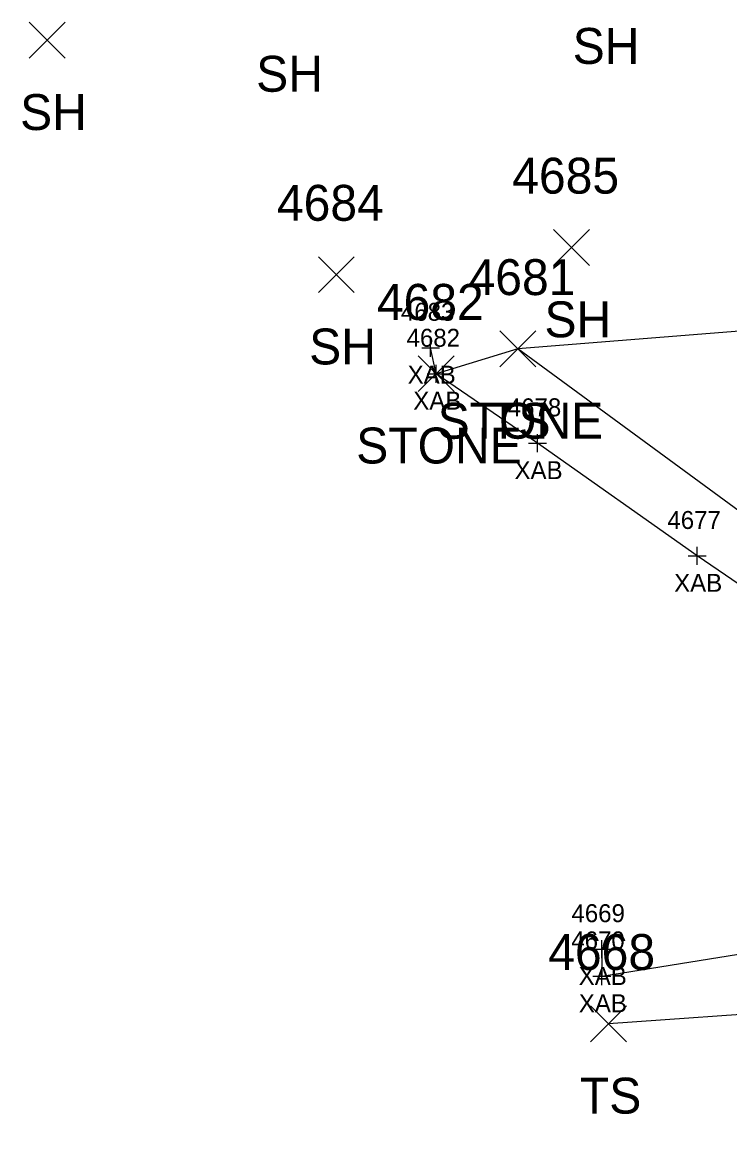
# Model space of a CAD drawing. Extents: x 1505656 to 1508446, y 700805 to 703031.
# Drawn here: x 1507022.6 to 1507061.9, y 701609.6 to 701671.6 of the extents above; entities that cross this region are included whole.
import ezdxf

# ---------------------------------------------------------------- set-up
doc = ezdxf.new("R2010")
doc.units = 0
for name, color, linetype in [('B_A', 7, 'Continuous'), ('B_I', 7, 'Continuous'), ('B_TIC', 7, 'Continuous'), ('BSUBM', 7, 'Continuous'), ('L_A', 7, 'Continuous'), ('L_I', 7, 'Continuous'), ('L_TIC', 7, 'Continuous'), ('LASF', 7, 'Continuous'), ('LELB', 7, 'Continuous')]:
    doc.layers.add(name, color=color, linetype=linetype)

msp = doc.modelspace()

# ---------------------------------------------------------------- linework, layer by layer
at = {"layer": 'B_TIC'}
for p, q in [((1507045.299, 701653.515), (1507045.374, 701653.515)), ((1507045.613, 701652.067), (1507045.688, 701652.067)), ((1507051.247, 701648.195), (1507051.323, 701648.195)), ((1507060.132, 701641.92), (1507060.207, 701641.92)), ((1507054.82, 701620.021), (1507054.895, 701620.021)), ((1507054.826, 701618.506), (1507054.901, 701618.506))]:
    msp.add_line(p, q, dxfattribs=at)
for points in [[(1507045.296, 701653.015), (1507045.296, 701654.015)], [(1507044.796, 701653.515), (1507045.796, 701653.515)], [(1507045.609, 701651.567), (1507045.609, 701652.567)], [(1507045.109, 701652.067), (1507046.109, 701652.067)], [(1507051.244, 701647.695), (1507051.244, 701648.695)], [(1507050.744, 701648.195), (1507051.744, 701648.195)], [(1507060.128, 701641.42), (1507060.128, 701642.42)], [(1507059.628, 701641.92), (1507060.628, 701641.92)], [(1507054.816, 701619.521), (1507054.816, 701620.521)], [(1507054.316, 701620.021), (1507055.316, 701620.021)], [(1507054.322, 701618.506), (1507055.322, 701618.506)], [(1507054.822, 701618.006), (1507054.822, 701619.006)]]:
    msp.add_lwpolyline(points, dxfattribs=at)
at = {"layer": 'BSUBM'}
msp.add_lwpolyline([(1507054.816, 701620.021), (1507054.822, 701618.506), (1507072.232, 701621.324), (1507084.922, 701623.311), (1507084.728, 701624.83), (1507078.817, 701628.967), (1507069.887, 701635.267), (1507060.128, 701641.92), (1507051.244, 701648.195), (1507045.609, 701652.067), (1507045.296, 701653.515)], dxfattribs=at)
at = {"layer": 'L_TIC'}
for points in [[(1507022.956, 701669.639), (1507024.956, 701671.639)], [(1507024.956, 701669.639), (1507022.956, 701671.639)], [(1507052.143, 701658.095), (1507054.143, 701660.095)], [(1507054.143, 701658.095), (1507052.143, 701660.095)], [(1507039.045, 701656.583), (1507041.045, 701658.583)], [(1507041.045, 701656.583), (1507039.045, 701658.583)], [(1507049.145, 701652.446), (1507051.145, 701654.446)], [(1507051.145, 701652.446), (1507049.145, 701654.446)], [(1507049.145, 701652.446), (1507051.145, 701654.446)], [(1507051.145, 701652.446), (1507049.145, 701654.446)], [(1507044.609, 701651.067), (1507046.609, 701653.067)], [(1507046.609, 701651.067), (1507044.609, 701653.067)], [(1507054.194, 701614.86), (1507056.194, 701616.86)], [(1507056.194, 701614.86), (1507054.194, 701616.86)]]:
    msp.add_lwpolyline(points, dxfattribs=at)
at = {"layer": 'LASF'}
msp.add_lwpolyline([(1507078.86, 701653.961), (1507068.999, 701654.953), (1507050.145, 701653.446), (1507045.609, 701652.067)], dxfattribs=at)
at = {"layer": 'LELB'}
for points in [[(1507091.83, 701624.828), (1507067.274, 701640.893), (1507050.145, 701653.446)], [(1507142.5, 701612.027), (1507115.939, 701613.729), (1507092.309, 701609.573), (1507076.307, 701618.116), (1507065.723, 701616.607), (1507055.194, 701615.86)]]:
    msp.add_lwpolyline(points, dxfattribs=at)

# ---------------------------------------------------------------- texts
at = {"layer": 'B_A'}
for p in [(1507044.016, 701651.515), (1507044.33, 701650.067), (1507049.964, 701646.195), (1507058.849, 701639.92), (1507053.537, 701618.021), (1507053.543, 701616.506)]:
    msp.add_text('XAB', height=1, dxfattribs=at).set_placement(p)
at = {"layer": 'B_I'}
for s, p in [('4683', (1507043.642, 701655.015)), ('4682', (1507043.956, 701653.567)), ('4678', (1507049.59, 701649.695)), ('4677', (1507058.475, 701643.42)), ('4669', (1507053.135, 701621.521)), ('4670', (1507053.125, 701620.006))]:
    msp.add_text(s, height=1, dxfattribs=at).set_placement(p)
at = {"layer": 'L_A'}
for s, p in [('SH', (1507053.202, 701669.323)), ('SH', (1507035.584, 701667.771)), ('SH', (1507022.444, 701665.639)), ('SH', (1507051.632, 701654.095)), ('SH', (1507038.534, 701652.583)), ('STONE', (1507045.688, 701648.446)), ('TS', (1507048.555, 701648.446)), ('STONE', (1507041.153, 701647.067)), ('TS', (1507053.604, 701610.86))]:
    msp.add_text(s, height=2, dxfattribs=at).set_placement(p)
at = {"layer": 'L_I'}
for s, p in [('4685', (1507049.836, 701662.095)), ('4684', (1507036.738, 701660.583)), ('4681', (1507047.405, 701656.446)), ('4681', (1507047.405, 701656.446)), ('4682', (1507042.302, 701655.067)), ('4668', (1507051.84, 701618.86))]:
    msp.add_text(s, height=2, dxfattribs=at).set_placement(p)

doc.saveas('drawing.dxf')
